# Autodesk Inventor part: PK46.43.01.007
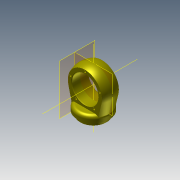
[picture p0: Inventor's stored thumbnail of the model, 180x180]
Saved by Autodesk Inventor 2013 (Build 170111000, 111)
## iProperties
Shininess: 20.0
Length Units: 11269
Angle Units: 11279
Time Units: 11290
Mass Units: 11283
Length Display Precision: 3
Angle Display Precision: 2
Created: 2001-08
Part Number: PK46.43.01.007
Material: Steel, Mild
Document SubType Name: Modeling
Designer: SOleg
Density: 7.86 g/cm^3
Density: 0.0
Volumn: 0.0
Area: 0.0
PropertySet Name: Model Information
Control State: 0
Master: False
Checked Out: True
Checked Out Date: 2008-10-09
Last Check In Date: 2008-10-09
Title: Крышка
Author: SOleg
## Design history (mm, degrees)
sketch "Эскиз13"
  geometry: L1 (38.884, -58.948)-(-23.616, -58.948); L2 (-23.616, -58.948)-(-23.616, -44.948); L3 (-23.616, -44.948)-(-24.616, -44.948); L4 (-24.616, -44.948)-(-24.616, -42.948); L5 (-24.616, -42.948)-(-37.116, -38.399); L6 (-37.116, -38.399)-(-37.116, -8.948); L7 (-37.116, -8.948)-(-49.128, 47.236); L8 (-51.116, 66.052)-(38.884, 66.052); L9 (38.884, 156.052)-(38.884, -58.948); L10 (-8.616, -58.948)-(-8.616, -31.948); L11 (-5.616, -28.948)-(38.884, -28.948); A1 r 90 centre (38.884, 66.052) between (38.884, 156.052) and (-49.128, 47.236); A2 r 3 centre (-5.616, -31.948) between (-5.616, -28.948) and (-8.616, -31.948); 1 further point
  constraints: 22 end point, 6 parallel, 5 point on circle, 5 point on line, 3 tangent, 2 centre point, 2 perpendicular, 1 coincident, 1 horizontal
  dimensions: "d142" = 90 radius of A1; "d143" = 30 distance between parallel lines of L11 L1; "d144" = 76 distance between parallel lines of L9 L6; "d145" = 47.5 distance of point (-8.616, -28.948) L11.end; "d146" = 62.5 distance between parallel lines of L9 L2; "d147" = 63.5 distance between parallel lines of L9 L4; "d148" = 20 deg angle of L3 L5; "d149" = 16 vertical distance of L1.end L4.end; "d150" = 14 distance of L1.end L2.end; "d151" = 3 radius of A2; "d163" = 125 distance from line of L1 L8.end; "d164" = 75 vertical distance of L6.end L8.end
revolve "Вращение6" sketch "Эскиз13" stored, may be unused: angle "d152" = 90 deg
node "РабОсь6"
sketch "Эскиз14"
  geometry: L1 (101.384, -58.948)-(-23.616, -58.948) reference; L2 (114.884, -38.399)-(-37.116, -38.399) reference; L3 (114.884, -38.399)-(114.884, -8.948) reference; L4 (-37.116, -38.399)-(-37.116, -8.948) reference; L5 (38.884, -101.948)-(38.884, 199.052) reference; L6 (78.884, 151.052)-(148.884, 151.052); L7 (148.884, 151.052)-(148.884, -8.948); L8 (148.884, -8.948)-(78.884, -8.948); L9 (78.884, -8.948)-(78.884, 151.052); L10 (-71.116, 151.052)-(-1.116, 151.052); L11 (-1.116, 151.052)-(-1.116, -8.948); L12 (-1.116, -8.948)-(-71.116, -8.948); L13 (-71.116, -8.948)-(-71.116, 151.052)
  constraints: 16 end point, 4 parallel, 2 horizontal, 2 perpendicular
  dimensions: "d153" = 160 distance of L6.end L7.end; "d154" = 160 distance of L12.end L10.start; "d155" = 0 distance from line of L8 L3.end; "d156" = 0 distance from line of L12 L4.end; "d157" = 40 distance between parallel lines of L5 L9; "d158" = 40 distance between parallel lines of L11 L5; "d159" = 70 distance of L6.start L6.end; "d160" = 70 distance of L10.start L10.end
extrude "Выдавливание3" cut sketch "Эскиз14" stored distance "d161" = 50; taper "d162" = 0 deg
node "РабПлоскость6"
sketch "Эскиз15"
  geometry: L1 (62.5, -35.275)-(-62.5, -35.275) reference; L2 (0, -78.275)-(0, 222.725) reference; 1 further point
  dimensions: "d165" = 0 distance from line of L2 point (0, 8.725); "d166" = 44 distance from line of L1 point (0, 8.725)
hole "Отверстие3" sketch "Эскиз15" diameter "d167" = 20; stored, may be unused: countersink angle "d171" = 82 deg, drill point angle "d173" = 118 deg; dims "d168" = 6, "d169" = 33, "d170" = 5, "d172" = 45
sketch "Эскиз16"
  geometry: C1 r 16.5 at (0, 0) reference; C2 r 10 at (0, 0) reference; C3 r 16.5 at (0, 0)
  constraints: 1 centre point, 1 coincident, 1 concentric
extrude "Выдавливание4" cut sketch "Эскиз16" stored distance "d174" = 50; taper "d175" = 0 deg
sketch "Эскиз17"
  geometry: C1 r 44.5 at (0, 0) reference; C2 r 10 at (31, 0)
  constraints: 1 centre point
  dimensions: "d176" = 0 vertical distance of C1.centre C2.centre; "d177" = 31 distance of C1.centre C2.centre; "d180" = 20 diameter of C2
extrude "Выдавливание5" cut sketch "Эскиз17" distance "d178" = 24; taper "d179" = 0 deg
sketch "Эскиз18"
  geometry: C1 r 62.5 at (0, 0); A1 r 80.623 centre (0, 0) between (78.396, -18.815) and (-78.396, -18.815) reference
  constraints: 1 centre point, 1 coincident
  dimensions: "d181" = 125 diameter of C1
extrude "Выдавливание6" cut sketch "Эскиз18" stored distance "d182" = 34; taper "d183" = 0 deg
sketch "Эскиз19" dims "d184" = 145
  geometry: L1 (0, -168)-(0, 133) reference; C1 r 5 at (0, 72.5); A1 r 80.623 centre (0, 0) between (78.396, -18.815) and (-78.396, -18.815) reference; 1 further point
  constraints: 1 centre point, 1 coincident, 1 point on line, 1 vertical alignment, 2 other
  dimensions: "d185" = 10 diameter of C1
extrude "Выдавливание7" cut sketch "Эскиз19" distance "d186" = 16; taper "d187" = 0 deg
chamfer "Фаска2" distance "d188" = 2; stored, may be unused: second distance "d189" = 2, angle "d196" = 45 deg
chamfer "Фаска3" distance "d190" = 2; stored, may be unused: second distance "d191" = 2, angle "d197" = 45 deg
node "РабОсь7"
pattern_circular "Круговой массив1" dims angle "d194" = 360 deg
node "РабПлоскость7"
mirror "ЗеркОтобр3"
fillet "Сопряжение4" dims "d198" = 15
body "Solid1"
other parameters: "d3" = 125 (derived), "d5" = 0 (derived), "d7" = 2 (derived), "d9" = 2 (derived), "d11" = 13 (derived), "d13" = 16 (derived), "d17" = 82.5 (derived), "d19" = 92.5 (derived), "d23" = 5 (derived), "d25" = 52.5 (derived), "d27" = 12.5 (derived), "d29" = 21.5 (derived), "d31" = 46 (derived), "d36" = 52.5 (derived), "d38" = 52.5 (derived), "d42" = 55 (derived), "d48" = 34 (derived), "d50" = 55 (derived), "d52" = 0 (derived), "d56" = 12.5 (derived), "d58" = 59 (derived), "d60" = 60 deg (derived), "d62" = 0 (derived), "d65" = 5 (derived), "d67" = 5 (derived), "d69" = 2 (derived), "d71" = 2 (derived), "d73" = 57.5 (derived), "d77" = 0 (derived)
